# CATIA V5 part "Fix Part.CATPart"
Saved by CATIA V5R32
Part number: Part4
Bounding box of the stored display mesh (mm): x -100 to 100, y -60 to 60, z -30 to 80.884
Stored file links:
  D:\PROJECTS\Project 2022\CATIA V5 6R 2022\Resources\Part Files\c16_catia_v5_6r2022_prt\Rack Joint(Fig16-57)\Fix Part.CATPart
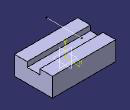
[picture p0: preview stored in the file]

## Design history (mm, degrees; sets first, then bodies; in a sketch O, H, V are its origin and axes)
Body1 (main body)
  Sketch1 on yz-plane, origin (0, 0, 0), H (0, 1, 0), V (0, 0, 1)
    line L1 (60, 30) -> (60, -30)
    line L2 (60, -30) -> (-60, -30)
    line L3 (-60, -30) -> (-60, 30)
    point P1 (60, 30)
    point P4 (-60, 30)
    point P5 (20, 30)
    line L4 (-20, 30) -> (-20, 14.3569)
    line L5 (-20, 14.3569) -> (20, 14.3569)
    line L6 (20, 14.3569) -> (20, 30)
    point P6 (-20, 30)
    point P7 (-20, 14.3569)
    point P8 (20, 14.3569)
    reference intersected line E1 through (0, 0) direction (-1, 0) from xy-plane
    reference intersected line E3 through (0, 0) direction (0, 1) from zx-plane
    line L7 (20, 30) -> (60, 30)
    line L8 (-20, 30) -> (-60, 30)
    reference intersected line E4 through (0, 0) direction (-1, 0) from xy-plane
    reference intersected line E6 through (0, 0) direction (0, 1) from zx-plane
    distance H L2 = 30
    distance V L1 = 60
    distance E1 L5 = 14.3569
    distance L4 L6 = 40
    distance P7 E3 = 20
    distance P5 P8 = 15.6431
    vertical: L1 V, L3 V, L4 V, L6 V, E3 V, E6 V
    horizontal: L2 H, L5 H, E1 H, L7 H, L8 H, E4 H
    equidistance: L1 L3 O
    perpendicularity: E1 L1
    coincidence: P1 L8, P4 L7, P5 L8, P6 L7, L7 L8
  Pad1: profile Sketch1, direction (1, 0, 0), length 100, mirrored extent
  Sketch2 on yz-plane, origin (0, 0, 0), H (0, 1, 0), V (0, 0, 1)
    line L1 (52.4742, 80.8837) -> (-58.5645, 80.8837)
    point P1 (52.4742, 80.8837)
    point P2 (-58.5645, 80.8837)
    distance P1 P2 = 111.0387
    horizontal: L1 H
